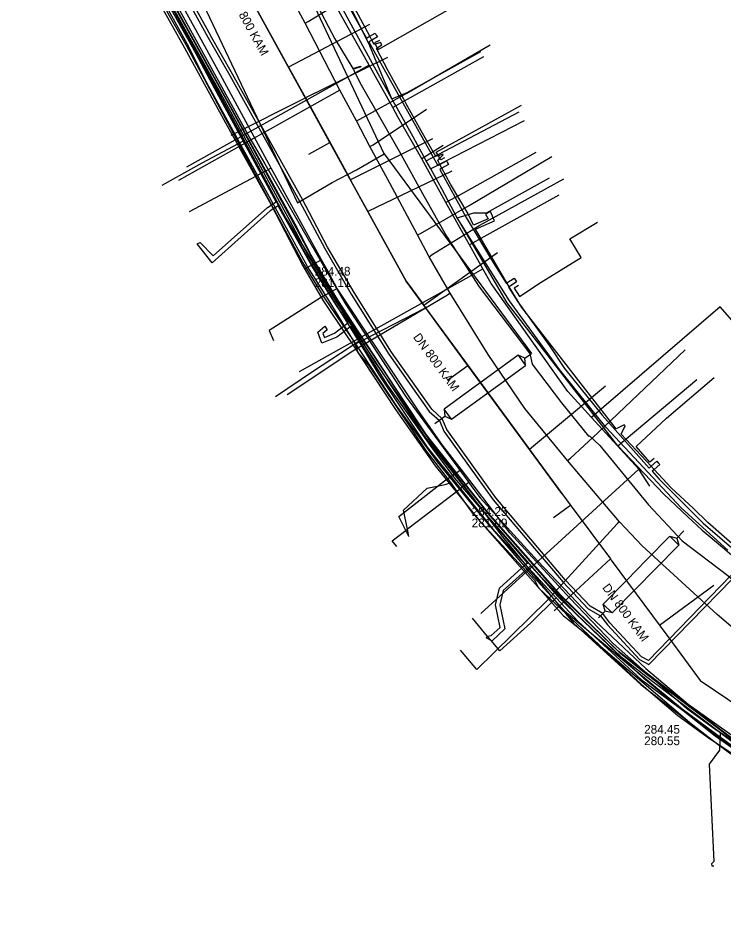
# Model space of a CAD drawing. Extents: x -600309 to -598967, y -1161267 to -1160292.
# Drawn here: x -599907.3 to -599842.7, y -1160599.1 to -1160516.4 of the extents above; entities that cross this region are included whole.
import ezdxf

# ---------------------------------------------------------------- set-up
doc = ezdxf.new("R2010")
doc.units = 0
for name, color, linetype in [('Vrstva 1', 7, 'Continuous'), ('Vrstva 12', 7, 'Continuous'), ('Vrstva 13', 7, 'Continuous'), ('Vrstva 16', 7, 'Continuous'), ('Vrstva 42', 7, 'Continuous'), ('Vrstva 44', 7, 'Continuous'), ('Vrstva 5', 7, 'Continuous'), ('Vrstva 54', 7, 'Continuous'), ('Vrstva 55', 7, 'Continuous'), ('Vrstva 58', 7, 'Continuous'), ('Vrstva 9', 7, 'Continuous')]:
    doc.layers.add(name, color=color, linetype=linetype)

msp = doc.modelspace()

# ---------------------------------------------------------------- linework, layer by layer
at = {"layer": 'Vrstva 1'}
for p, q in [((-599880.66, -1160528.83), (-599878.734, -1160527.773)), ((-599867.97, -1160549.54), (-599866.113, -1160548.177)), ((-599858.27, -1160562.1), (-599856.729, -1160560.959)), ((-599843.62, -1160568.32), (-599848.57, -1160571.983))]:
    msp.add_line(p, q, dxfattribs=at)
for points in [[(-599857.52, -1160559.89), (-599866.111, -1160548.18), (-599871.76, -1160540.48), (-599878.734, -1160527.773), (-599886.327, -1160513.932), (-599890.764, -1160505.846), (-599893.889, -1160500), (-599898.969, -1160490.471), (-599901.936, -1160484.905), (-599902.158, -1160484.489), (-599906.15, -1160477), (-599907.435, -1160475.222), (-599915.237, -1160464.873), (-599922.471, -1160455.22), (-599931.32, -1160443.41), (-599941.55, -1160433.12), (-599946.993, -1160427.644), (-599952.415, -1160422.19), (-599953.381, -1160421.219)], [(-599880.66, -1160528.83), (-599878.734, -1160527.773)], [(-599867.97, -1160549.54), (-599866.11, -1160548.18)], [(-599858.27, -1160562.1), (-599856.729, -1160560.959)], [(-599843.62, -1160568.32), (-599848.57, -1160571.983)]]:
    msp.add_lwpolyline(points, dxfattribs=at)
at = {"layer": 'Vrstva 12'}
for points in [[(-599884.11, -1160530.12), (-599888.75, -1160521.59), (-599890.19, -1160518.96), (-599903.71, -1160494.36)], [(-599867.68, -1160558.91), (-599869.93, -1160555.96), (-599875.17, -1160548.16), (-599876.14, -1160547), (-599876.47, -1160546.11), (-599878.66, -1160542.51), (-599880.8, -1160539.13), (-599889.99, -1160522.32), (-599891.79, -1160518.75), (-599901.31, -1160501.54)], [(-599895.59, -1160510.02), (-599886.08, -1160527.37)], [(-599873.07, -1160523.78), (-599877.86, -1160515.01)], [(-599873.07, -1160523.78), (-599871.66, -1160523.19), (-599864.93, -1160519.45)], [(-599869.93, -1160529.46), (-599871.13, -1160527.25), (-599872.58, -1160524.63), (-599873.07, -1160523.78)], [(-599869.93, -1160529.46), (-599861.41, -1160524.95)], [(-599860.96, -1160525.8), (-599869.49, -1160530.19)], [(-599886.08, -1160527.37), (-599884.69, -1160529.72)], [(-599884.69, -1160529.72), (-599877.34, -1160542.52), (-599871.83, -1160550.99), (-599866.04, -1160558.89)], [(-599869.49, -1160530.19), (-599869.93, -1160529.46)], [(-599884.11, -1160530.12), (-599891.61, -1160534.13)], [(-599879.51, -1160538.51), (-599884.11, -1160530.12)], [(-599867.08, -1160534.66), (-599868.49, -1160532), (-599869.49, -1160530.19)], [(-599865.56, -1160534.2), (-599864.4, -1160534.2), (-599858.63, -1160531.01)], [(-599867.08, -1160534.66), (-599865.56, -1160534.2)], [(-599864.75, -1160538.65), (-599866.87, -1160534.99), (-599867.08, -1160534.66)], [(-599879.51, -1160538.51), (-599881.04, -1160539.35)], [(-599878.06, -1160541.15), (-599879.02, -1160539.37), (-599879.51, -1160538.51)], [(-599852.38, -1160555.55), (-599862.53, -1160542.46), (-599864.75, -1160538.65)], [(-599878.06, -1160541.15), (-599879.6, -1160541.99), (-599884.29, -1160544.97), (-599883.9, -1160545.89)], [(-599866.72, -1160557.69), (-599868.43, -1160555.47), (-599870.7, -1160552.25), (-599878.06, -1160541.15)], [(-599852.38, -1160555.55), (-599845.17, -1160549.46)], [(-599852.38, -1160555.55), (-599848.19, -1160559.97), (-599845.98, -1160562.03), (-599844.68, -1160563.25), (-599842.81, -1160564.83), (-599841.32, -1160566.09), (-599840.85, -1160566.46)], [(-599871.52, -1160563.83), (-599872.42, -1160562.01), (-599868.26, -1160558.74), (-599866.99, -1160557.88), (-599866.72, -1160557.69)], [(-599843.04, -1160581.78), (-599843.38, -1160581.56), (-599846.12, -1160579.58), (-599852.83, -1160573.64), (-599856.78, -1160569.48), (-599857.8, -1160568.38), (-599862.27, -1160563.51), (-599866.72, -1160557.69)], [(-599867.1, -1160559.71), (-599867.68, -1160558.91)], [(-599866.04, -1160558.89), (-599865.74, -1160559.29)], [(-599865.74, -1160559.29), (-599864.99, -1160560.31), (-599859.74, -1160566.07), (-599854.91, -1160571.14), (-599849.83, -1160575.91)], [(-599852.1, -1160575.66), (-599859.62, -1160568.57), (-599860, -1160567.87), (-599865.59, -1160561.79), (-599867.1, -1160559.71)], [(-599852.1, -1160575.66), (-599850.24, -1160577.4), (-599846.9, -1160580.23), (-599843.99, -1160582.32), (-599835.05, -1160588.21), (-599832.33, -1160589.94), (-599829.32, -1160591.75), (-599827.31, -1160591.43)], [(-599849.83, -1160575.91), (-599845.97, -1160579.18), (-599838.83, -1160584.25), (-599834.41, -1160587.2), (-599828.09, -1160590.97)], [(-599843.04, -1160581.78), (-599843.08, -1160583.39), (-599844.03, -1160584.68), (-599843.62, -1160593.58), (-599843.81, -1160593.79), (-599843.8, -1160593.99), (-599843.6, -1160593.98)], [(-599821.67, -1160595.25), (-599822.83, -1160594.22), (-599824.54, -1160593.42), (-599833.89, -1160587.97), (-599843.04, -1160581.78)]]:
    msp.add_lwpolyline(points, dxfattribs=at)
at = {"layer": 'Vrstva 13'}
for points in [[(-599843.3, -1160570.99), (-599845.79, -1160568.7), (-599850.15, -1160564.7), (-599852.25, -1160562.49), (-599856.99, -1160556.88), (-599860.91, -1160552.13), (-599864.27, -1160547.18), (-599867.74, -1160541.56), (-599869.65, -1160538.23), (-599870.71, -1160536.23), (-599873.26, -1160531.5), (-599875.07, -1160528.14), (-599876.3, -1160525.8), (-599877.82, -1160522.98), (-599881, -1160516.855), (-599882.2, -1160514.62), (-599886.52, -1160506.84), (-599887.06, -1160505.88), (-599889.41, -1160501.71), (-599895.2, -1160491.32), (-599901.16, -1160480.96)], [(-599881, -1160516.855), (-599880.725, -1160516.709), (-599876.66, -1160514.18), (-599867.849, -1160509.43)], [(-599875.08, -1160518.91), (-599877.42, -1160514.16)], [(-599876.3, -1160525.8), (-599876.01, -1160525.64), (-599871.69, -1160523.26), (-599864.084, -1160518.826)], [(-599874.65, -1160519.96), (-599875.08, -1160518.91)], [(-599873.07, -1160523.78), (-599874.65, -1160519.96)], [(-599877.82, -1160522.98), (-599878.1, -1160523.12), (-599892.596, -1160531.243)], [(-599875.07, -1160528.14), (-599874.794, -1160527.98), (-599869.903, -1160524.71)], [(-599870.71, -1160536.23), (-599870.44, -1160536.09), (-599865.99, -1160533.53), (-599858.426, -1160529.06)], [(-599869.65, -1160538.23), (-599869.38, -1160538.03), (-599865.03, -1160535.34), (-599857.342, -1160531.091)], [(-599842.33, -1160565.09), (-599846.61, -1160561.22), (-599853.48, -1160553.82), (-599857.73, -1160548.56), (-599862.31, -1160542.26), (-599867.08, -1160534.66)], [(-599867.74, -1160541.56), (-599867.97, -1160541.74), (-599876.64, -1160546.86), (-599882.644, -1160550.867)], [(-599856.99, -1160556.88), (-599856.72, -1160556.66), (-599854.23, -1160554.35), (-599846.229, -1160546.757)], [(-599871.65, -1160563.18), (-599871.99, -1160561.43), (-599869.84, -1160559.42), (-599868.18, -1160559.07), (-599867.68, -1160558.91)], [(-599866.62, -1160559.33), (-599867.1, -1160559.71)], [(-599866.04, -1160558.89), (-599866.62, -1160559.33)], [(-599867.31, -1160559.87), (-599871.65, -1160563.18)], [(-599867.1, -1160559.71), (-599867.31, -1160559.87)], [(-599852.25, -1160562.49), (-599852.45, -1160562.67), (-599858.87, -1160569.69), (-599865.28, -1160576.02), (-599866.774, -1160574.24)], [(-599872.62, -1160564.75), (-599873.05, -1160564.25), (-599871.65, -1160563.18)], [(-599871.52, -1160563.83), (-599871.65, -1160563.18)], [(-599815.98, -1160587.08), (-599816.39, -1160586.87), (-599822, -1160583.72), (-599827.25, -1160580.9), (-599830.01, -1160579.46), (-599835.52, -1160576.6), (-599838.52, -1160575.08), (-599843.3, -1160570.99)]]:
    msp.add_lwpolyline(points, dxfattribs=at)
at = {"layer": 'Vrstva 16'}
for points in [[(-599849.46, -1160559.23), (-599850.48, -1160557.69), (-599854.8, -1160552.96), (-599856.97, -1160550.57), (-599863.99, -1160540.67), (-599864.73, -1160539.35), (-599865.96, -1160537.14), (-599868.12, -1160533.28), (-599870.32, -1160529.26), (-599872.48, -1160525.48), (-599872.99, -1160524.56), (-599875.15, -1160520.7), (-599877.76, -1160516.03), (-599879.03, -1160513.76), (-599887.17, -1160499.19), (-599895.46, -1160484.36), (-599901.24, -1160474.94)], [(-599864.68, -1160519.92), (-599871.68, -1160523.83), (-599872.99, -1160524.56)], [(-599875.15, -1160520.7), (-599891.85, -1160530.03)], [(-599868.37, -1160528.05), (-599870.32, -1160529.26)], [(-599859.91, -1160528.69), (-599866.81, -1160532.55), (-599868.12, -1160533.28)], [(-599857.79, -1160532.58), (-599864.65, -1160536.41), (-599865.96, -1160537.14)], [(-599866.04, -1160540.08), (-599864.73, -1160539.35)], [(-599881.52, -1160548.74), (-599866.04, -1160540.08)], [(-599841.92, -1160544.08), (-599843.02, -1160542.81), (-599853.66, -1160551.98), (-599854.8, -1160552.96)], [(-599850.48, -1160557.69), (-599864.93, -1160570.88)]]:
    msp.add_lwpolyline(points, dxfattribs=at)
at = {"layer": 'Vrstva 42'}
for points in [[(-599898.24, -1160502.99), (-599889.91, -1160518.14), (-599887.91, -1160521.65), (-599881.51, -1160533.13), (-599879.21, -1160537.49), (-599876.79, -1160541.65), (-599873.36, -1160547.14), (-599869.65, -1160552.39), (-599868.712, -1160553.232), (-599868.31, -1160554.19), (-599863.8, -1160560.48), (-599857.43, -1160568), (-599855.1, -1160570.46), (-599853.98, -1160571.11), (-599853.34, -1160571.94), (-599850.41, -1160575.09), (-599849.54, -1160575.55), (-599841.94, -1160567.75)], [(-599898.24, -1160502.99), (-599889.91, -1160518.14), (-599887.91, -1160521.65), (-599881.51, -1160533.13), (-599879.21, -1160537.49), (-599876.79, -1160541.65), (-599873.36, -1160547.14), (-599869.65, -1160552.39), (-599868.712, -1160553.232), (-599868.31, -1160554.19), (-599863.8, -1160560.48), (-599857.43, -1160568), (-599855.1, -1160570.46), (-599853.98, -1160571.11), (-599853.34, -1160571.94), (-599850.41, -1160575.09), (-599849.54, -1160575.55), (-599841.94, -1160567.75)], [(-599842.037, -1160567.42), (-599849.598, -1160575.18), (-599850.225, -1160574.849), (-599853.111, -1160571.746), (-599853.778, -1160570.88), (-599854.912, -1160570.222), (-599857.206, -1160567.8), (-599863.563, -1160560.295), (-599868.046, -1160554.043), (-599868.461, -1160553.054), (-599869.424, -1160552.189), (-599873.11, -1160546.974), (-599876.533, -1160541.495), (-599878.948, -1160537.345), (-599881.246, -1160532.987), (-599887.649, -1160521.503), (-599889.649, -1160517.991), (-599889.647, -1160517.995), (-599897.979, -1160502.841)], [(-599842.037, -1160567.42), (-599849.598, -1160575.18), (-599850.225, -1160574.849), (-599853.111, -1160571.746), (-599853.778, -1160570.88), (-599854.912, -1160570.222), (-599857.206, -1160567.8), (-599863.563, -1160560.295), (-599868.046, -1160554.043), (-599868.461, -1160553.054), (-599869.424, -1160552.189), (-599873.11, -1160546.974), (-599876.533, -1160541.495), (-599878.948, -1160537.345), (-599881.246, -1160532.987), (-599887.649, -1160521.503), (-599889.649, -1160517.991), (-599889.647, -1160517.995), (-599897.979, -1160502.841)], [(-599874.099, -1160518.627), (-599874.589, -1160518.778), (-599874.696, -1160518.811), (-599874.91, -1160518.405), (-599875.096, -1160518.051), (-599876.117, -1160516.11), (-599877.562, -1160513.507), (-599880.274, -1160508.589), (-599881.853, -1160505.637), (-599881.817, -1160505.602), (-599881.462, -1160505.258), (-599881.537, -1160505.18)], [(-599880.011, -1160509.913), (-599875.385, -1160518.214), (-599875.096, -1160518.051), (-599874.591, -1160517.766), (-599874.492, -1160517.94), (-599874.394, -1160518.114), (-599874.91, -1160518.405), (-599875.191, -1160518.563), (-599873.97, -1160520.754), (-599870.009, -1160527.807), (-599868.874, -1160529.886), (-599868.676, -1160529.777), (-599868.065, -1160529.443), (-599867.968, -1160529.619), (-599867.872, -1160529.794), (-599868.484, -1160530.129), (-599868.682, -1160530.238), (-599866.275, -1160534.646), (-599863.943, -1160538.501), (-599862.601, -1160540.664), (-599862.551, -1160540.632), (-599861.872, -1160540.199), (-599861.765, -1160540.368), (-599861.657, -1160540.536), (-599862.342, -1160540.974), (-599862.39, -1160541.004), (-599861.542, -1160542.372), (-599858.654, -1160546.385), (-599857.261, -1160548.455), (-599853.835, -1160552.73), (-599849.517, -1160557.574), (-599849.343, -1160557.415), (-599848.83, -1160556.948), (-599848.695, -1160557.095), (-599848.56, -1160557.243), (-599849.071, -1160557.708), (-599849.251, -1160557.872), (-599848.608, -1160558.593), (-599844.591, -1160562.612), (-599840.011, -1160566.554)], [(-599894.872, -1160512.655), (-599890.771, -1160520.047), (-599889.123, -1160523.018), (-599884.336, -1160531.966), (-599880.45, -1160538.878), (-599878.12, -1160542.69), (-599877.12, -1160544.326), (-599876.911, -1160544.669), (-599876.101, -1160545.993), (-599874.218, -1160549.074), (-599869.828, -1160555.666), (-599863.934, -1160563.053), (-599860.832, -1160566.411), (-599860.56, -1160566.705), (-599858.022, -1160569.452), (-599856.024, -1160571.615), (-599850.251, -1160576.928), (-599846.907, -1160579.413), (-599840.336, -1160584.296), (-599832.764, -1160589.502), (-599833.231, -1160590.274)], [(-599879.195, -1160544.584), (-599879.002, -1160544.92), (-599879.376, -1160545.253), (-599879.244, -1160545.611), (-599878.308, -1160545.236), (-599877.12, -1160544.326), (-599877.049, -1160544.271), (-599878.12, -1160542.69), (-599878.668, -1160541.881), (-599880.394, -1160539.07), (-599883.461, -1160533.555), (-599884.216, -1160534.035), (-599889.51, -1160538.775), (-599890.895, -1160537.061), (-599890.617, -1160536.923), (-599889.42, -1160538.157), (-599884.46, -1160533.716), (-599883.664, -1160533.211), (-599889.681, -1160522.074), (-599890.771, -1160520.047), (-599891.309, -1160519.047), (-599894.872, -1160512.655)], [(-599874.211, -1160518.421), (-599874.656, -1160518.66), (-599874.589, -1160518.778), (-599874.403, -1160519.105), (-599874.317, -1160519.256), (-599866.411, -1160514.783)], [(-599868.406, -1160528.84), (-599868.815, -1160528.979), (-599869.056, -1160529.061), (-599870.386, -1160526.711), (-599871.752, -1160524.229), (-599871.967, -1160523.794), (-599873.403, -1160521.208), (-599874.48, -1160519.155), (-599874.403, -1160519.105), (-599873.988, -1160518.835), (-599874.099, -1160518.627)], [(-599868.239, -1160529.163), (-599868.6, -1160529.362), (-599868.682, -1160529.216), (-599868.815, -1160528.979), (-599869.002, -1160528.646), (-599861.203, -1160524.352)], [(-599886.668, -1160527.66), (-599890.46, -1160529.664), (-599894.129, -1160531.715)], [(-599864.044, -1160534.097), (-599864.5, -1160534.326), (-599864.254, -1160534.745), (-599865.601, -1160535.344), (-599866.088, -1160534.316), (-599867.69, -1160531.585), (-599868.484, -1160530.129), (-599868.676, -1160529.777), (-599868.871, -1160529.419), (-599868.682, -1160529.216), (-599868.388, -1160528.9), (-599868.406, -1160528.84)], [(-599851.817, -1160553.617), (-599852.543, -1160553.983), (-599861.168, -1160542.89), (-599862.342, -1160540.974), (-599862.551, -1160540.632), (-599862.744, -1160540.318), (-599865.412, -1160535.697), (-599863.682, -1160534.928), (-599864.044, -1160534.097)], [(-599861.475, -1160540.863), (-599861.865, -1160541.099), (-599861.399, -1160541.855), (-599859.409, -1160540.547), (-599855.761, -1160538.296), (-599856.778, -1160536.587), (-599854.256, -1160535.056)], [(-599836.783, -1160586.818), (-599843.475, -1160582.105), (-599846.577, -1160579.687), (-599846.907, -1160579.413), (-599850.007, -1160576.839), (-599856.165, -1160570.949), (-599860.377, -1160566.54), (-599860.56, -1160566.705), (-599862.869, -1160568.781), (-599863.178, -1160570.108), (-599862.729, -1160572.295), (-599863.912, -1160573.407), (-599863.983, -1160573.367), (-599864.453, -1160573.103), (-599864.309, -1160572.981), (-599864.275, -1160572.952), (-599863.973, -1160572.915), (-599863.166, -1160572.156), (-599863.588, -1160570.103), (-599863.23, -1160568.568), (-599860.832, -1160566.411), (-599860.657, -1160566.254), (-599867.317, -1160558.504), (-599869.389, -1160555.735), (-599873.459, -1160549.959), (-599876.826, -1160544.604), (-599876.911, -1160544.669), (-599878.108, -1160545.586), (-599879.477, -1160546.135), (-599879.845, -1160545.136), (-599879.195, -1160544.584)], [(-599876.096, -1160545.99), (-599876.101, -1160545.993), (-599880.242, -1160548.691), (-599883.706, -1160551.04)], [(-599849.075, -1160556.711), (-599849.452, -1160557.04), (-599850.72, -1160555.598), (-599847.943, -1160553.005), (-599843.572, -1160549.298)], [(-599821.363, -1160575.54), (-599823.141, -1160577.829), (-599827.207, -1160575.361), (-599828.753, -1160574.423), (-599835.09, -1160570.128), (-599839.903, -1160566.27), (-599844.158, -1160562.552), (-599845.457, -1160561.284), (-599847.509, -1160559.388), (-599849.071, -1160557.708), (-599849.343, -1160557.415), (-599852.072, -1160554.48), (-599851.727, -1160553.718), (-599851.817, -1160553.617)], [(-599858.01, -1160569.44), (-599858.022, -1160569.452), (-599860.356, -1160571.75), (-599863.203, -1160574.291), (-599863.983, -1160573.367), (-599864.309, -1160572.981), (-599865.704, -1160571.329)]]:
    msp.add_lwpolyline(points, dxfattribs=at)
at = {"layer": 'Vrstva 44'}
for points in [[(-599822.087, -1160609.959), (-599823.257, -1160596.559), (-599823.317, -1160594.899), (-599824.147, -1160593.929), (-599830.537, -1160590.099), (-599838.397, -1160585.039), (-599839.967, -1160583.829), (-599849.397, -1160576.629), (-599852.347, -1160574.339), (-599857.637, -1160569.179), (-599864.267, -1160561.679), (-599869.897, -1160554.529), (-599876.777, -1160544.179), (-599877.967, -1160542.299), (-599880.457, -1160538.099), (-599881.927, -1160535.259), (-599888.357, -1160523.519), (-599895.337, -1160510.869)], [(-599895.98, -1160512.07), (-599892.05, -1160519.1), (-599888.28, -1160525.98), (-599884.1, -1160533.47), (-599881.23, -1160539.05), (-599879.4, -1160542.21), (-599877.211, -1160545.448), (-599876.71, -1160546.19), (-599872.74, -1160552.22), (-599869.1, -1160557.37), (-599865.03, -1160562.45), (-599857.4, -1160571.06), (-599855.42, -1160572.67), (-599844.98, -1160581.56), (-599839.17, -1160585.81), (-599835.32, -1160588.31), (-599830.56, -1160591.26), (-599825.85, -1160593.68), (-599824.7, -1160594.78), (-599824.18, -1160595.55), (-599823.91, -1160596.26), (-599823.5, -1160603.2)], [(-599895.93, -1160511.8), (-599891.93, -1160518.81), (-599884.19, -1160533.27), (-599881.2, -1160538.78), (-599879.3, -1160541.93)], [(-599879.3, -1160541.93), (-599876.967, -1160545.346), (-599876.63, -1160545.84), (-599872.65, -1160551.91), (-599868.91, -1160556.99), (-599864.77, -1160562.09), (-599860.36, -1160567.26), (-599857.26, -1160570.65), (-599855.42, -1160572.21), (-599850.47, -1160576.35), (-599846.51, -1160579.63), (-599842.88, -1160582.29), (-599838.97, -1160585.12), (-599835.18, -1160587.73), (-599830.37, -1160590.49), (-599823.85, -1160594.71), (-599823.44, -1160595.33), (-599823.31, -1160596), (-599822.8, -1160603.02)]]:
    msp.add_lwpolyline(points, dxfattribs=at)
at = {"layer": 'Vrstva 5'}
msp.add_line((-599853.518, -1160550.071), (-599860.469, -1160555.87), dxfattribs=at)
at = {"layer": 'Vrstva 54'}
for points in [[(-599873.76, -1160528.82), (-599886.66, -1160501.41)], [(-599894.9, -1160505.44), (-599881.71, -1160533.31)], [(-599876.29, -1160530.26), (-599873.76, -1160528.82)], [(-599873.76, -1160528.82), (-599860.29, -1160547.08)], [(-599878.54, -1160531.42), (-599876.29, -1160530.26)], [(-599881.71, -1160533.31), (-599878.54, -1160531.42)], [(-599860.904, -1160547.525), (-599860.29, -1160547.08)], [(-599861.512, -1160547.252), (-599864.11, -1160549.13)], [(-599860.834, -1160548.188), (-599860.904, -1160547.525), (-599861.512, -1160547.252), (-599860.834, -1160548.188)], [(-599863.39, -1160550.04), (-599860.834, -1160548.188)], [(-599864.11, -1160549.13), (-599866.34, -1160550.75)], [(-599865.63, -1160551.66), (-599863.39, -1160550.04)], [(-599866.34, -1160550.75), (-599868.298, -1160552.169)], [(-599867.62, -1160553.105), (-599868.298, -1160552.169), (-599868.228, -1160552.832), (-599867.62, -1160553.105)], [(-599867.62, -1160553.105), (-599865.63, -1160551.66)], [(-599869.15, -1160553.5), (-599868.228, -1160552.832)], [(-599846.34, -1160563.31), (-599846.995, -1160563.979)], [(-599849.79, -1160566.01), (-599847.64, -1160563.812)], [(-599848.94, -1160566.79), (-599846.814, -1160564.621)], [(-599846.814, -1160564.621), (-599847.64, -1160563.812), (-599846.995, -1160563.979), (-599846.814, -1160564.621)], [(-599851.57, -1160567.83), (-599849.79, -1160566.01)], [(-599850.73, -1160568.62), (-599848.94, -1160566.79)], [(-599853.73, -1160570.033), (-599851.57, -1160567.83)], [(-599852.904, -1160570.842), (-599850.73, -1160568.62)], [(-599853.73, -1160570.033), (-599852.904, -1160570.842), (-599853.549, -1160570.675), (-599853.73, -1160570.033)], [(-599853.549, -1160570.675), (-599854.16, -1160571.3)]]:
    msp.add_lwpolyline(points, dxfattribs=at)
at = {"layer": 'Vrstva 55'}
for points in [[(-599880.139, -1160514.74), (-599878.289, -1160518.28), (-599876.65, -1160520.987), (-599876.035, -1160520.8), (-599875.89, -1160520.82), (-599875.98, -1160520.89), (-599876.608, -1160521.063), (-599875.88, -1160522.49), (-599872.389, -1160528.58), (-599870.12, -1160532.71), (-599868.059, -1160536.35), (-599865.09, -1160541), (-599860.469, -1160547.07), (-599860.39, -1160547.16), (-599860.42, -1160547.242), (-599860.22, -1160548.06), (-599857.55, -1160551.59), (-599855.08, -1160554.67), (-599854.99, -1160554.62)], [(-599854.99, -1160554.62), (-599854.04, -1160555.5), (-599849.6, -1160560.93), (-599846.5, -1160564.23), (-599842.34, -1160567.41), (-599836.14, -1160572.72), (-599835.53, -1160572.87), (-599830.9, -1160574.94), (-599826.66, -1160576.79), (-599812.72, -1160583.91), (-599805.44, -1160587.49), (-599799.47, -1160590.02), (-599798.76, -1160590.06), (-599794.55, -1160590.16), (-599791.05, -1160588.25), (-599791.37, -1160587.42), (-599790.5, -1160586.88), (-599785.83, -1160583.3), (-599779.31, -1160578.94), (-599776.23, -1160575.89), (-599774.72, -1160572.96), (-599774.64, -1160569.54), (-599766.89, -1160569.33), (-599766.71, -1160568.47)]]:
    msp.add_lwpolyline(points, dxfattribs=at)
at = {"layer": 'Vrstva 58'}
for points in [[(-599897.04, -1160508.42), (-599889.28, -1160522.54), (-599882.76, -1160534.71), (-599874.66, -1160547.81), (-599869.52, -1160555.17), (-599862.95, -1160563.88), (-599856.45, -1160571.76), (-599850.28, -1160577.38), (-599843.22, -1160582.88), (-599837.76, -1160586.88), (-599831.27, -1160590.51), (-599825.74, -1160593.61), (-599825.33, -1160593.95), (-599824.58, -1160594.94), (-599823.78, -1160597.23), (-599822.55, -1160607.18)], [(-599895.47, -1160511.178), (-599888.574, -1160523.607), (-599882.205, -1160535.326), (-599880.664, -1160538.227), (-599878.177, -1160542.348), (-599876.939, -1160544.276), (-599870.088, -1160554.687), (-599864.453, -1160561.863), (-599857.869, -1160569.328), (-599852.415, -1160574.593), (-599849.817, -1160576.638), (-599840.039, -1160584.043), (-599838.532, -1160585.207), (-599830.63, -1160590.304), (-599824.272, -1160594.195), (-599823.685, -1160595.514), (-599823.456, -1160596.583), (-599822.616, -1160607.557)], [(-599895.342, -1160511.014), (-599888.399, -1160523.511), (-599882.028, -1160535.232), (-599880.489, -1160538.131), (-599878.017, -1160542.249), (-599876.775, -1160544.162), (-599869.925, -1160554.57), (-599864.3, -1160561.735), (-599857.724, -1160569.19), (-599852.283, -1160574.442), (-599849.696, -1160576.48), (-599839.919, -1160583.886), (-599838.413, -1160585.045), (-599830.523, -1160590.134), (-599824.114, -1160594.057), (-599823.494, -1160595.452), (-599823.257, -1160596.555), (-599822.417, -1160607.541)]]:
    msp.add_lwpolyline(points, dxfattribs=at)
at = {"layer": 'Vrstva 9'}
for p, q in [((-599875.13, -1160516.96), (-599882.517, -1160520.875)), ((-599873.48, -1160520), (-599880.978, -1160523.681)), ((-599887.78, -1160527.11), (-599880.978, -1160523.681)), ((-599869.35, -1160527.44), (-599876.858, -1160531.196)), ((-599867.58, -1160530.4), (-599875.267, -1160534.098)), ((-599863.41, -1160537.88), (-599870.14, -1160542.688)), ((-599876.85, -1160546.44), (-599869.986, -1160542.898)), ((-599858.23, -1160570.65), (-599853.077, -1160565.893))]:
    msp.add_line(p, q, dxfattribs=at)
for points in [[(-599891.08, -1160505.27), (-599890.554, -1160506.228), (-599886.327, -1160513.932), (-599886.303, -1160513.977), (-599882.519, -1160520.872), (-599882.517, -1160520.875), (-599880.978, -1160523.681), (-599880.938, -1160523.754), (-599880.852, -1160523.911), (-599878.178, -1160528.788), (-599876.858, -1160531.196), (-599876.818, -1160531.27), (-599875.267, -1160534.098), (-599875.198, -1160534.222), (-599871.76, -1160540.48)], [(-599871.76, -1160540.48), (-599870.311, -1160542.455), (-599870.216, -1160542.584), (-599870.14, -1160542.688), (-599869.986, -1160542.898), (-599865.904, -1160548.462), (-599860.627, -1160555.654), (-599860.469, -1160555.87), (-599857.52, -1160559.89)], [(-599857.52, -1160559.89), (-599856.652, -1160561.062), (-599853.077, -1160565.893), (-599852.994, -1160566.006), (-599847.723, -1160573.128), (-599844.85, -1160577.01)], [(-599844.85, -1160577.01), (-599835.874, -1160583.097), (-599835.609, -1160583.276), (-599829.7, -1160587.283), (-599829.617, -1160587.34), (-599815.952, -1160596.606), (-599815.795, -1160596.712), (-599812.592, -1160598.884), (-599812.551, -1160598.912), (-599810.515, -1160600.293), (-599810.225, -1160600.489), (-599809, -1160601.32)]]:
    msp.add_lwpolyline(points, dxfattribs=at)

# ---------------------------------------------------------------- texts
at = {"layer": 'Vrstva 12'}
for rotation, p in [(298.75392, (-599887.995, -1160514.444)), (306.26535, (-599871.163, -1160545.599)), (306.50404, (-599853.854, -1160568.528))]:
    msp.add_text('DN 800 KAM', height=0.8, rotation=rotation, dxfattribs=at).set_placement(p)
for s, p in [('284.48', (-599880.125, -1160539.955)), ('281.11', (-599880.125, -1160541.005)), ('284.25', (-599865.764, -1160561.948)), ('281.09', (-599865.764, -1160562.998)), ('284.45', (-599849.981, -1160581.89)), ('280.55', (-599849.981, -1160582.94))]:
    msp.add_text(s, height=0.8, dxfattribs=at).set_placement(p)

doc.saveas('drawing.dxf')
